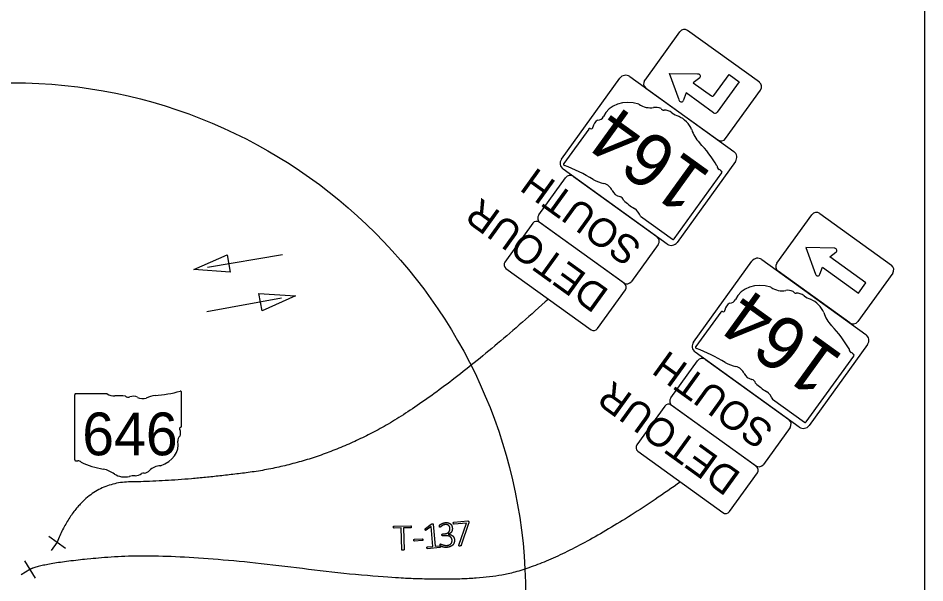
# Model space of a CAD drawing. Extents: x -740 to 1519, y 0 to 440.
# Drawn here: x 191 to 350, y 120.5 to 219.6 of the extents above; entities that cross this region are included whole.
import ezdxf

# ---------------------------------------------------------------- set-up
doc = ezdxf.new("R2010")
doc.units = 0
for name, color, linetype in [('Default', 7, 'Continuous'), ('GM_X_County_Road_Text', 7, 'Continuous'), ('GM_X_Minor_Lake', 7, 'Continuous'), ('GM_X_Minor_River', 7, 'Continuous'), ('GM_X_Section', 7, 'Continuous'), ('GM_X_Township_Text', 7, 'Continuous'), ('SH_Data', 7, 'Continuous')]:
    doc.layers.add(name, color=color, linetype=linetype)

msp = doc.modelspace()

# ---------------------------------------------------------------- linework, layer by layer
at = {"layer": 'Default'}
for p, q in [((224.24, 175.91), (237.36, 178.14)), ((237.19, 170.43), (224.1, 168.04))]:
    msp.add_line(p, q, dxfattribs=at)
for points in [[(228.2, 175), (221.79, 175.49), (227.67, 178.08)], [(233.23, 171.29), (239.65, 170.88), (233.79, 168.22)]]:
    msp.add_lwpolyline(points, close=True, dxfattribs=at)
at = {"layer": 'GM_X_County_Road_Text'}
for p, q in [((200.92, 153.46), (200.92, 142.08)), ((206.6, 153.66), (201.11, 153.66)), ((219.67, 147.98), (219.67, 153.94)), ((219.67, 147.99), (219.67, 147.98))]:
    msp.add_line(p, q, dxfattribs=at)
for centre, major_axis, start_param, end_param in [((201.14, 153.49), (0.217, 0), 1.712693, 3.28349), ((207.91, 154.98), (2.11, 0), 4.042523, 4.731795), ((208.6, 147.27), (7.56, 0), 1.404758, 1.657858), ((210.32, 153.55), (0.608, 0), 3.836095, 5.185415), ((211.21, 152.23), (1.26, 0), 0.950623, 2.079405), ((212.84, 154.03), (1.52, 0), 4.081561, 5.145723), ((215.53, 150.18), (4, 0), 1.699011, 2.107814), ((212.99, 169.18), (19.88, 0), 4.814394, 5.042369), ((219.46, 153.96), (0.209, 0), 6.141152, 7.989035), ((219.45, 147.96), (0.223, 0), 5.05454, 6.418171), ((219.62, 147.55), (0.323, 0), 1.883978, 3.671073), ((217.57, 146.79), (1.94, 0), 5.934695, 6.695948), ((214.11, 144.73), (4.97, 0), 5.101752, 6.440018), ((220.42, 145.49), (1.41, 0), 2.387724, 3.262537), ((201.14, 142.05), (0.219, 0), 3.00124, 4.508301), ((201.17, 143.22), (1.67, 0), 4.665946, 4.897461), ((201.51, 141.42), (0.603, 0), 0.519207, 1.627899), ((209.13, 151.65), (14.36, 0), 4.195997, 4.488961), ((204.85, 136.96), (4.49, 0), 0.823519, 1.323587), ((212.75, 140.97), (1.61, 0), 4.937069, 5.64225), ((216.2, 138.88), (2.72, 0), 1.647645, 2.488434), ((209.71, 141.36), (2.85, 0), 4.026481, 4.996735), ((211.35, 137.43), (2.34, 0), 1.495662, 1.94098), ((211.56, 140.51), (1.52, 0), 4.691044, 5.507374), ((212.94, 139.41), (0.428, 0), 1.147584, 2.315152)]:
    msp.add_ellipse(centre, major_axis=major_axis, ratio=0.8, start_param=start_param, end_param=end_param, dxfattribs=at)
at = {"layer": 'GM_X_Minor_Lake'}
for p, q in [((324.03, 176.57), (330.17, 185.09)), ((331.57, 185.31), (344.14, 176.24)), ((334.07, 179.25), (329.13, 179.37)), ((329.13, 179.37), (330.82, 174.64)), ((333.32, 177.69), (334.39, 178.5)), ((339.65, 173.12), (333.32, 177.69)), ((336.83, 166.11), (324.26, 175.17)), ((331.61, 174.65), (332.04, 175.92)), ((332.04, 175.92), (338.37, 171.35)), ((344.37, 174.85), (338.22, 166.33)), ((338.37, 171.35), (339.65, 173.12))]:
    msp.add_line(p, q, dxfattribs=at)
for centre, radius, start, end in [((330.98, 184.5), 1, 54.1903, 144.1903), ((334.14, 178.83), 0.417, 306.9856, 99.1998), ((324.84, 175.99), 1, 144.1903, 234.1903), ((343.55, 175.43), 1, 324.1903, 54.1903), ((331.21, 174.78), 0.417, 199.6015, 341.3949), ((337.41, 166.92), 1, 234.1903, 324.1903)]:
    msp.add_arc(centre, radius, start, end, dxfattribs=at)
at = {"layer": 'GM_X_Minor_River'}
for p, q in [((307, 217.2), (300.87, 208.68)), ((320.98, 208.37), (308.4, 217.43)), ((306.89, 205.25), (305.21, 209.9)), ((305.21, 209.9), (310.16, 209.79)), ((310.56, 209.13), (309.4, 208.23)), ((313.01, 206.02), (315.66, 209.7)), ((317.43, 208.42), (313.6, 203.09)), ((315.66, 209.7), (317.43, 208.42)), ((301.09, 207.29), (313.67, 198.23)), ((309.4, 208.23), (312.57, 205.95)), ((315.07, 198.45), (321.2, 206.97)), ((308.13, 206.46), (307.64, 205.07)), ((312.94, 202.99), (308.13, 206.46)), ((312.94, 202.99), (312.94, 202.99)), ((291.05, 200.13), (286.7, 194.09)), ((291.05, 200.12), (291.05, 200.13)), ((306.06, 180.87), (314.38, 192.42)), ((282.32, 185.07), (286.99, 191.56)), ((288.39, 191.79), (303, 181.27)), ((300.16, 184.82), (305.73, 180.81)), ((297.15, 173.15), (282.55, 183.67)), ((303.22, 179.87), (298.55, 173.38)), ((314.2, 168.02), (309.85, 161.99)), ((314.2, 168.02), (314.2, 168.02)), ((305.46, 152.97), (310.14, 159.46)), ((311.54, 159.69), (326.14, 149.16)), ((329.2, 148.76), (337.53, 160.3)), ((323.31, 152.71), (328.87, 148.69)), ((320.29, 141.05), (305.69, 151.58)), ((326.36, 147.76), (321.68, 141.27)), ((196.37, 128.69), (199.29, 126.58)), ((197.83, 127.64), (196.78, 126.18)), ((192.12, 124.38), (194.02, 121.32)), ((193.07, 122.85), (191.54, 121.9))]:
    msp.add_line(p, q, dxfattribs=at)
for points in [[(286.28, 194.85), (296.51, 209.05)], [(298.25, 209.33), (316.51, 196.18)], [(316.79, 194.44), (306.57, 180.24)], [(304.82, 179.95), (286.56, 193.1)], [(281.27, 183.61), (276.36, 176.79)], [(297.31, 173.04), (282.38, 183.79)], [(309.43, 162.75), (319.67, 176.94)], [(321.42, 177.22), (339.66, 164.06)], [(276.54, 175.68), (291.47, 164.92)], [(292.58, 165.1), (297.49, 171.92)], [(339.95, 162.31), (329.71, 148.12)], [(327.96, 147.84), (309.72, 161)], [(304.41, 151.51), (299.5, 144.7)], [(320.45, 140.93), (305.53, 151.69)], [(299.68, 143.58), (314.6, 132.82)], [(315.72, 133), (320.63, 139.81)]]:
    msp.add_lwpolyline(points, dxfattribs=at)
for centre, radius, start, end in [((307.82, 216.62), 1, 54.2326, 144.2326), ((297.52, 208.32), 1.25, 54.2326, 144.2326), ((301.68, 208.1), 1, 144.2326, 234.2326), ((310.23, 209.37), 0.417, 324.231, 99.2325), ((320.39, 207.56), 1, 324.2326, 54.2326), ((307.3, 205.32), 0.417, 189.2328, 324.231), ((312.76, 206.2), 0.312, 234.2326, 324.2326), ((313.22, 203.37), 0.469, 234.2326, 324.2326), ((314.26, 199.04), 1, 234.2326, 324.2326), ((315.78, 195.17), 1.25, 324.2326, 54.2326), ((287.3, 194.12), 1.25, 144.2326, 234.2326), ((287.81, 190.98), 1, 54.2326, 144.2326), ((283.13, 184.49), 1, 144.2326, 234.2326), ((281.92, 183.14), 0.8, 54.2326, 144.2326), ((302.41, 180.46), 1, 324.2326, 54.2326), ((305.55, 180.97), 1.25, 234.2326, 324.2326), ((277.01, 176.33), 0.8, 144.2326, 234.2326), ((320.69, 176.21), 1.25, 54.1903, 144.1903), ((297.74, 173.97), 1, 234.2326, 324.2326), ((296.85, 172.39), 0.8, 324.2326, 54.2326), ((291.94, 165.57), 0.8, 234.2326, 324.2326), ((338.93, 163.04), 1.25, 324.1903, 54.1903), ((310.45, 162.02), 1.25, 144.1903, 234.1903), ((310.96, 158.88), 1, 54.1903, 144.1903), ((306.28, 152.39), 1, 144.1903, 234.1903), ((305.06, 151.05), 0.8, 54.1903, 144.1903), ((325.55, 148.34), 1, 324.1903, 54.1903), ((328.69, 148.85), 1.25, 234.1903, 324.1903), ((300.14, 144.23), 0.8, 144.1903, 234.1903), ((320.87, 141.86), 1, 234.1903, 324.1903), ((319.98, 140.28), 0.8, 324.1903, 54.1903), ((315.07, 133.47), 0.8, 234.1903, 324.1903)]:
    msp.add_arc(centre, radius, start, end, dxfattribs=at)
for centre, major_axis, start_param, end_param in [((299.07, 199.36), (-5.04, 3.63), 5.101752, 6.440018), ((301.22, 206.83), (-2.76, 1.99), 1.647645, 2.488434), ((303.19, 202.18), (-1.63, 1.17), 4.937069, 5.64225), ((304.15, 203.9), (-0.434, 0.312), 1.147584, 2.315152), ((292.11, 203.2), (-1.43, 1.03), 2.387724, 3.262537), ((304.73, 201.78), (-1.54, 1.11), 4.691044, 5.507374), ((307.2, 204.76), (-2.38, 1.71), 1.495662, 1.94098), ((305.99, 199.56), (-2.89, 2.08), 4.026481, 4.996735), ((291.42, 200.53), (-0.328, 0.236), 1.883978, 3.671073), ((294.05, 199.8), (-1.97, 1.42), 5.934695, 6.695948), ((291.29, 199.99), (-0.227, 0.163), 5.05454, 6.418171), ((314.14, 200.47), (-4.56, 3.28), 0.823519, 1.323587), ((299.06, 188.71), (-14.56, 10.49), 4.195997, 4.488961), ((286.89, 193.91), (-0.212, 0.153), 6.141152, 7.989035), ((282.34, 173.75), (-20.17, 14.53), 4.814394, 5.042369), ((314.26, 193.52), (-0.612, 0.441), 0.519207, 1.627899), ((313.29, 191.45), (-1.7, 1.22), 4.665946, 4.897461), ((314.18, 192.6), (-0.222, 0.16), 3.00124, 4.508301), ((293.64, 194.87), (-4.06, 2.92), 1.699011, 2.107814), ((293.55, 189), (-1.54, 1.11), 4.081561, 5.145723), ((296.52, 189.64), (-1.28, 0.92), 0.950623, 2.079405), ((296.47, 187.65), (-0.616, 0.444), 3.836095, 5.185415), ((302.8, 192.77), (-7.67, 5.53), 1.404758, 1.657858), ((297.87, 184.44), (-2.14, 1.54), 4.042523, 4.731795), ((305.83, 181), (-0.22, 0.159), 1.712693, 3.28349), ((322.22, 167.25), (-5.04, 3.64), 5.101752, 6.440018), ((324.38, 174.71), (-2.76, 1.99), 1.647645, 2.488434), ((326.35, 170.07), (-1.63, 1.18), 4.937069, 5.64225), ((315.27, 171.1), (-1.43, 1.03), 2.387724, 3.262537), ((327.3, 171.79), (-0.434, 0.313), 1.147584, 2.315152), ((327.89, 169.67), (-1.54, 1.11), 4.691044, 5.507374), ((330.36, 172.64), (-2.37, 1.71), 1.495662, 1.94098), ((329.15, 167.45), (-2.89, 2.09), 4.026481, 4.996735), ((317.21, 167.69), (-1.97, 1.42), 5.934695, 6.695948), ((314.45, 167.88), (-0.226, 0.163), 5.05454, 6.418171), ((314.57, 168.43), (-0.327, 0.236), 1.883978, 3.671073), ((337.29, 168.35), (-4.55, 3.29), 0.823519, 1.323587), ((322.21, 156.6), (-14.56, 10.5), 4.195997, 4.488961), ((310.04, 161.81), (-0.212, 0.153), 6.141152, 7.989035), ((305.47, 141.65), (-20.16, 14.54), 4.814394, 5.042369), ((337.41, 161.4), (-0.611, 0.441), 0.519207, 1.627899), ((336.44, 159.33), (-1.7, 1.22), 4.665946, 4.897461), ((337.33, 160.48), (-0.222, 0.16), 3.00124, 4.508301), ((316.8, 162.77), (-4.06, 2.93), 1.699011, 2.107814), ((316.7, 156.9), (-1.54, 1.11), 4.081561, 5.145723), ((319.67, 157.53), (-1.28, 0.92), 0.950623, 2.079405), ((319.62, 155.55), (-0.616, 0.445), 3.836095, 5.185415), ((325.95, 160.66), (-7.67, 5.53), 1.404758, 1.657858), ((321.02, 152.33), (-2.14, 1.54), 4.042523, 4.731795), ((328.97, 148.89), (-0.22, 0.159), 1.712693, 3.28349)]:
    msp.add_ellipse(centre, major_axis=major_axis, ratio=0.8, start_param=start_param, end_param=end_param, dxfattribs=at)
at = {"layer": 'GM_X_Section'}
msp.add_line((350, 10), (350, 430), dxfattribs=at)
at = {"layer": 'GM_X_Township_Text'}
for p, q in [((256.92, 130.45), (259.85, 130.52)), ((262.46, 130.06), (263.42, 130.79)), ((267.42, 131.14), (269.85, 131.36)), ((269.99, 130.91), (268.72, 127.1)), ((270.02, 131.2), (270.02, 131.2)), ((259.95, 130.34), (259.95, 130.34)), ((265.43, 129.07), (265.8, 129.1)), ((266.42, 129.03), (266.42, 129.02)), ((260.49, 128.14), (261.86, 128.24)), ((261.88, 127.91), (260.51, 127.81)), ((261.96, 128.08), (261.96, 128.08)), ((265.88, 128.76), (265.46, 128.72)), ((267.52, 128.09), (267.52, 128.09)), ((264.95, 126.67), (262.81, 126.49)), ((265.05, 126.84), (265.05, 126.84))]:
    msp.add_line(p, q, dxfattribs=at)
for points in [[(263.8, 130.77), (264.12, 126.93), (264.93, 127)], [(268.29, 127.09), (269.62, 130.98), (267.45, 130.79)], [(258.28, 126.31), (258.19, 130.12), (256.92, 130.1)], [(259.86, 130.16), (258.59, 130.13), (258.68, 126.31)], [(262.78, 126.82), (263.72, 126.9), (263.43, 130.37), (262.58, 129.75)]]:
    msp.add_lwpolyline(points, dxfattribs=at)
for points in [[(256.82, 130.35), (256.83, 130.38), (256.84, 130.4)], [(256.84, 130.4), (256.85, 130.43), (256.87, 130.44)], [(256.87, 130.44), (256.89, 130.45), (256.92, 130.45)], [(259.85, 130.52), (259.87, 130.52), (259.89, 130.51)], [(259.89, 130.51), (259.91, 130.5), (259.92, 130.47)], [(259.92, 130.47), (259.94, 130.45), (259.95, 130.42)], [(259.95, 130.42), (259.95, 130.38), (259.95, 130.34)], [(263.42, 130.79), (263.43, 130.8), (263.45, 130.8)], [(263.45, 130.8), (263.46, 130.81), (263.49, 130.82)], [(263.49, 130.82), (263.51, 130.83), (263.54, 130.83)], [(263.54, 130.83), (263.56, 130.83), (263.6, 130.84)], [(263.6, 130.84), (263.65, 130.84), (263.69, 130.84)], [(263.69, 130.84), (263.73, 130.83), (263.76, 130.83)], [(263.76, 130.83), (263.78, 130.82), (263.79, 130.8)], [(263.79, 130.8), (263.8, 130.79), (263.8, 130.77)], [(264.87, 130.49), (264.87, 130.52), (264.88, 130.54)], [(264.87, 130.42), (264.87, 130.46), (264.87, 130.49)], [(264.89, 130.33), (264.88, 130.37), (264.87, 130.42)], [(264.88, 130.54), (264.89, 130.56), (264.9, 130.59)], [(264.9, 130.59), (264.91, 130.61), (264.94, 130.64)], [(264.94, 130.64), (264.96, 130.67), (265.05, 130.74)], [(265.05, 130.74), (265.14, 130.81), (265.26, 130.87)], [(265.28, 130.47), (265.16, 130.39), (265.08, 130.32)], [(265.26, 130.87), (265.39, 130.94), (265.56, 130.99)], [(265.55, 130.62), (265.39, 130.55), (265.28, 130.47)], [(265.91, 130.71), (265.71, 130.7), (265.55, 130.62)], [(265.56, 130.99), (265.72, 131.05), (265.92, 131.06)], [(266.25, 130.69), (266.1, 130.73), (265.91, 130.71)], [(265.92, 131.06), (266.21, 131.09), (266.43, 131.03)], [(266.5, 130.56), (266.39, 130.65), (266.25, 130.69)], [(266.43, 131.03), (266.65, 130.97), (266.8, 130.85)], [(266.66, 130.34), (266.6, 130.47), (266.5, 130.56)], [(266.8, 130.85), (266.95, 130.72), (267.04, 130.54)], [(267.04, 130.54), (267.12, 130.36), (267.14, 130.14)], [(267.32, 130.95), (267.31, 131), (267.32, 131.03)], [(267.32, 131.03), (267.32, 131.06), (267.34, 131.09)], [(267.36, 130.83), (267.32, 130.88), (267.32, 130.95)], [(267.34, 131.09), (267.35, 131.11), (267.37, 131.13)], [(267.45, 130.79), (267.39, 130.78), (267.36, 130.83)], [(267.37, 131.13), (267.39, 131.14), (267.42, 131.14)], [(269.85, 131.36), (269.9, 131.36), (269.93, 131.35)], [(269.93, 131.35), (269.96, 131.35), (269.97, 131.33)], [(269.97, 131.33), (269.99, 131.3), (270, 131.27)], [(270.01, 130.98), (270, 130.95), (269.99, 130.91)], [(270, 131.27), (270.02, 131.24), (270.02, 131.2)], [(270.02, 131.05), (270.02, 131.02), (270.01, 130.98)], [(270.02, 131.2), (270.02, 131.16), (270.02, 131.12)], [(270.02, 131.12), (270.02, 131.09), (270.02, 131.05)], [(256.82, 130.27), (256.82, 130.31), (256.82, 130.35)], [(256.83, 130.19), (256.82, 130.22), (256.82, 130.27)], [(256.85, 130.14), (256.83, 130.16), (256.83, 130.19)], [(256.88, 130.11), (256.86, 130.12), (256.85, 130.14)], [(256.92, 130.1), (256.9, 130.09), (256.88, 130.11)], [(259.9, 130.17), (259.88, 130.16), (259.86, 130.16)], [(259.93, 130.21), (259.92, 130.19), (259.9, 130.17)], [(259.95, 130.26), (259.94, 130.23), (259.93, 130.21)], [(259.95, 130.34), (259.95, 130.29), (259.95, 130.26)], [(262.4, 129.92), (262.4, 129.96), (262.41, 129.98)], [(262.4, 129.85), (262.4, 129.89), (262.4, 129.92)], [(262.42, 129.76), (262.41, 129.8), (262.4, 129.85)], [(262.41, 129.98), (262.42, 130), (262.43, 130.02)], [(262.45, 129.71), (262.43, 129.72), (262.42, 129.76)], [(262.43, 130.02), (262.44, 130.04), (262.46, 130.06)], [(262.5, 129.7), (262.47, 129.7), (262.45, 129.71)], [(262.58, 129.75), (262.53, 129.71), (262.5, 129.7)], [(264.91, 130.28), (264.89, 130.3), (264.89, 130.33)], [(264.94, 130.26), (264.92, 130.26), (264.91, 130.28)], [(264.97, 130.25), (264.95, 130.25), (264.94, 130.26)], [(265.08, 130.32), (265.01, 130.26), (264.97, 130.25)], [(265.33, 128.96), (265.34, 129), (265.35, 129.02)], [(265.33, 128.89), (265.32, 128.93), (265.33, 128.96)], [(265.35, 128.81), (265.33, 128.84), (265.33, 128.89)], [(265.35, 129.02), (265.37, 129.04), (265.39, 129.05)], [(265.38, 128.76), (265.36, 128.78), (265.35, 128.81)], [(265.39, 129.05), (265.41, 129.06), (265.43, 129.07)], [(265.8, 129.1), (266.03, 129.12), (266.21, 129.2)], [(266.21, 129.2), (266.39, 129.28), (266.51, 129.4)], [(266.75, 129.18), (266.61, 129.08), (266.42, 129.03)], [(266.42, 129.02), (266.64, 129.02), (266.83, 128.95)], [(266.51, 129.4), (266.63, 129.53), (266.69, 129.7)], [(266.73, 130.07), (266.71, 130.21), (266.66, 130.34)], [(266.69, 129.7), (266.75, 129.87), (266.73, 130.07)], [(266.99, 129.43), (266.9, 129.29), (266.75, 129.18)], [(266.83, 128.95), (267.02, 128.88), (267.17, 128.76)], [(267.12, 129.76), (267.08, 129.58), (266.99, 129.43)], [(267.14, 130.14), (267.16, 129.94), (267.12, 129.76)], [(260.4, 127.97), (260.39, 128.06), (260.42, 128.1)], [(260.44, 127.84), (260.41, 127.87), (260.4, 127.97)], [(260.42, 128.1), (260.44, 128.13), (260.49, 128.14)], [(260.51, 127.81), (260.47, 127.81), (260.44, 127.84)], [(261.86, 128.24), (261.88, 128.24), (261.89, 128.23)], [(261.95, 127.95), (261.92, 127.91), (261.88, 127.91)], [(261.89, 128.23), (261.91, 128.23), (261.93, 128.21)], [(261.93, 128.21), (261.94, 128.19), (261.95, 128.16)], [(261.95, 128.16), (261.96, 128.13), (261.96, 128.08)], [(261.96, 128.08), (261.97, 127.99), (261.95, 127.95)], [(265.03, 127.15), (265.02, 127.25), (265.04, 127.28)], [(265.04, 127.28), (265.06, 127.32), (265.09, 127.33)], [(265.09, 127.33), (265.12, 127.33), (265.22, 127.28)], [(265.22, 127.28), (265.31, 127.23), (265.46, 127.18)], [(265.42, 128.73), (265.4, 128.74), (265.38, 128.76)], [(265.46, 128.72), (265.45, 128.72), (265.42, 128.73)], [(266.36, 128.74), (266.15, 128.78), (265.88, 128.76)], [(266.74, 128.6), (266.58, 128.7), (266.36, 128.74)], [(266.63, 127.17), (266.8, 127.25), (266.91, 127.37)], [(266.99, 128.34), (266.9, 128.49), (266.74, 128.6)], [(266.91, 127.37), (267.02, 127.49), (267.07, 127.65)], [(267.1, 128), (267.08, 128.19), (266.99, 128.34)], [(267.07, 127.65), (267.11, 127.81), (267.1, 128)], [(267.17, 128.76), (267.32, 128.64), (267.41, 128.47)], [(267.47, 127.58), (267.4, 127.34), (267.24, 127.16)], [(267.41, 128.47), (267.5, 128.3), (267.52, 128.09)], [(267.52, 128.09), (267.54, 127.82), (267.47, 127.58)], [(258.29, 126.27), (258.28, 126.29), (258.28, 126.31)], [(258.32, 126.24), (258.3, 126.25), (258.29, 126.27)], [(258.38, 126.23), (258.34, 126.23), (258.32, 126.24)], [(258.48, 126.22), (258.42, 126.22), (258.38, 126.23)], [(258.57, 126.23), (258.53, 126.23), (258.48, 126.22)], [(258.63, 126.25), (258.61, 126.24), (258.57, 126.23)], [(258.67, 126.28), (258.66, 126.26), (258.63, 126.25)], [(258.68, 126.31), (258.68, 126.29), (258.67, 126.28)], [(262.69, 126.71), (262.7, 126.75), (262.71, 126.77)], [(262.69, 126.64), (262.69, 126.68), (262.69, 126.71)], [(262.71, 126.57), (262.69, 126.6), (262.69, 126.64)], [(262.71, 126.77), (262.72, 126.79), (262.74, 126.81)], [(262.74, 126.52), (262.72, 126.53), (262.71, 126.57)], [(262.74, 126.81), (262.76, 126.82), (262.78, 126.82)], [(262.77, 126.49), (262.76, 126.5), (262.74, 126.52)], [(262.81, 126.49), (262.79, 126.48), (262.77, 126.49)], [(264.93, 127), (264.95, 127), (264.97, 126.99)], [(264.99, 126.68), (264.97, 126.67), (264.95, 126.67)], [(264.97, 126.99), (264.99, 126.98), (265.01, 126.96)], [(265.03, 126.71), (265.01, 126.69), (264.99, 126.68)], [(265.01, 126.96), (265.03, 126.94), (265.04, 126.91)], [(265.04, 127.06), (265.04, 127.1), (265.03, 127.15)], [(265.05, 126.76), (265.04, 126.73), (265.03, 126.71)], [(265.06, 127), (265.05, 127.02), (265.04, 127.06)], [(265.04, 126.91), (265.05, 126.88), (265.05, 126.84)], [(265.05, 126.84), (265.06, 126.79), (265.05, 126.76)], [(265.09, 126.96), (265.07, 126.98), (265.06, 127)], [(265.12, 126.92), (265.1, 126.94), (265.09, 126.96)], [(265.25, 126.86), (265.15, 126.9), (265.12, 126.92)], [(265.49, 126.78), (265.35, 126.82), (265.25, 126.86)], [(265.46, 127.18), (265.61, 127.13), (265.8, 127.09)], [(265.83, 126.72), (265.64, 126.74), (265.49, 126.78)], [(265.8, 127.09), (265.99, 127.05), (266.22, 127.07)], [(266.22, 126.72), (266.01, 126.7), (265.83, 126.72)], [(266.22, 127.07), (266.46, 127.09), (266.63, 127.17)], [(266.82, 126.87), (266.57, 126.75), (266.22, 126.72)], [(267.24, 127.16), (267.08, 126.98), (266.82, 126.87)], [(268.28, 127.02), (268.28, 127.05), (268.29, 127.09)], [(268.29, 126.98), (268.27, 127), (268.28, 127.02)], [(268.35, 126.96), (268.31, 126.96), (268.29, 126.98)], [(268.47, 126.96), (268.39, 126.95), (268.35, 126.96)], [(268.57, 126.97), (268.53, 126.96), (268.47, 126.96)], [(268.64, 126.99), (268.61, 126.98), (268.57, 126.97)], [(268.69, 127.04), (268.67, 127.01), (268.64, 126.99)], [(268.72, 127.1), (268.7, 127.06), (268.69, 127.04)]]:
    msp.add_open_spline(points, degree=2, dxfattribs=at)
at = {"layer": 'SH_Data'}
msp.add_circle((190, 118.25), 90, dxfattribs=at)
for points in [[(284, 170.3), (265.06, 153.2), (242.81, 141.32), (219.25, 138.3), (202.09, 138.11), (197.83, 127.64)], [(307.14, 138.2), (286.07, 123.29), (263.63, 120.08), (218.25, 125.88), (195.58, 124.08), (193.07, 122.85)]]:
    msp.add_open_spline(points, degree=2, dxfattribs=at)

# ---------------------------------------------------------------- texts
at = {"layer": 'GM_X_County_Road_Text'}
msp.add_text('646', height=7.5, dxfattribs=at).set_placement((202.25, 142.88))
at = {"layer": 'GM_X_Minor_River'}
for s, height, rotation, p in [('164', 9.375, 144.2326, (312.86, 192.28)), ('SOUTH', 5, 144.2326, (300.65, 179.87)), ('DETOUR', 5, 144.2326, (294.85, 171.73)), ('164', 9.375, 144.1903, (336.01, 160.16)), ('SOUTH', 5, 144.1903, (323.79, 147.76)), ('DETOUR', 5, 144.1903, (317.99, 139.62))]:
    msp.add_text(s, height=height, rotation=rotation, dxfattribs=at).set_placement(p)

doc.saveas('drawing.dxf')
